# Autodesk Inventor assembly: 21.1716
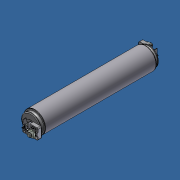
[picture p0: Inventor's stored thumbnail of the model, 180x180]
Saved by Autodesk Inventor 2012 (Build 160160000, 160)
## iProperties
Created: 2007-07
Part Number: 21.1716
Document SubType Name: Assembly
Designer: Andy Moles
Description: TRANSPORT ROLLER AL
Author: Andy Moles
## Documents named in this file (3)
- Y:\INVENTOR LIBRARIES\PARTS LIBRARY\BELT AND ROLLER CONVEYORS\21.1716 TRANSPORT ROLLER AL.iam
- Y:\INVENTOR LIBRARIES\PARTS LIBRARY\BELT AND ROLLER CONVEYORS\SUBCOMPONENTS\20.1041 TRANSPORT ROLLER ALUMINUM TUBE.ipt
- Y:\INVENTOR LIBRARIES\PARTS LIBRARY\BELT AND ROLLER CONVEYORS\21.1056 BEARING ASSEMBLY FOR TRANSPORT ROLLERS.iam
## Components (3 placed, 2 different names)
1. 20.1041 TRANSPORT ROLLER ALUMINUM TUBE:1 — Mate:1, Mate:2, Mate:3, Insert:1, Insert:2
2. 21.1056 BEARING ASSEMBLY FOR TRANSPORT ROLLERS:1 [sub-assembly] — Insert:1, Angle:1
3. 21.1056 BEARING ASSEMBLY FOR TRANSPORT ROLLERS:2 [sub-assembly] — Insert:2, Angle:2
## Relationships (7: Mate 3, Insert 2, Angle 2)
- Mate:1: 20.1041 TRANSPORT ROLLER ALUMINUM TUBE:1
- Mate:2: 20.1041 TRANSPORT ROLLER ALUMINUM TUBE:1
- Mate:3: 20.1041 TRANSPORT ROLLER ALUMINUM TUBE:1
- Insert:1: 20.1041 TRANSPORT ROLLER ALUMINUM TUBE:1 ↔ 21.1056 BEARING ASSEMBLY FOR TRANSPORT ROLLERS:1
- Insert:2: 20.1041 TRANSPORT ROLLER ALUMINUM TUBE:1 ↔ 21.1056 BEARING ASSEMBLY FOR TRANSPORT ROLLERS:2
- Angle:1: 21.1056 BEARING ASSEMBLY FOR TRANSPORT ROLLERS:1
- Angle:2: 21.1056 BEARING ASSEMBLY FOR TRANSPORT ROLLERS:2
